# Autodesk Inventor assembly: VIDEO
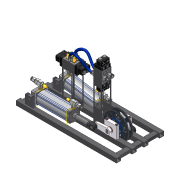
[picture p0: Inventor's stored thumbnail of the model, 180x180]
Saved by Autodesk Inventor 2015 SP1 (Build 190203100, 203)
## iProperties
Created: 2015-05
Part Number: VIDEO
Document SubType Name: Assembly
Designer: TREINA11
Author: TREINA11
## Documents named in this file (2)
- C:\Users\TREINA11\Desktop\#01- Polymechanics and Automation\01 - 3D Models\Pneumatic System\VIDEO.iam
- C:\Users\TREINA11\Desktop\#01- Polymechanics and Automation\01 - 3D Models\Pneumatic System\Teljes hajtás (Video).iam
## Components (1 placed, 1 different names)
1. Teljes hajtás (Video):1 [sub-assembly] — Mate:1, Flush:1, Mate:2
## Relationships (3: Mate 2, Flush 1)
- Mate:1: Teljes hajtás (Video):1
- Flush:1: Teljes hajtás (Video):1
- Mate:2: Teljes hajtás (Video):1
